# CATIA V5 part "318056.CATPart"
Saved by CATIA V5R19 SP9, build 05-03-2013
Part number: 318056
Source: Unknown
Bounding box of the stored display mesh (mm): x -689.306 to 68.166, y -250.508 to -117.73, z 198.129 to 590.152
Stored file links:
  D:\16-SIL\kale oto\R19_V2\318056.CATPart
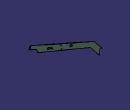
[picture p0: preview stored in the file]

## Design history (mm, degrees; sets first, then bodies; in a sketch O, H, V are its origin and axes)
Body1 "157\\126\\MANIFOLD_SOLID_BREP #79669" (main body)
  Solid1: solid without history
Body2 "241\\216\\MANIFOLD_SOLID_BREP #154205"
  Solid2: solid without history
Body3 "241\\217\\MANIFOLD_SOLID_BREP #153170"
  Solid3: solid without history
